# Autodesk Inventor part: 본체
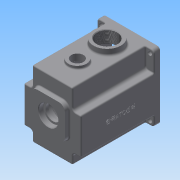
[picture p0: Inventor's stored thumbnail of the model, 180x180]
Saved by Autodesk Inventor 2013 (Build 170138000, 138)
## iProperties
Created: 2016-02
Part Number: 본체
Material: 알루미늄 6061
Document SubType Name: Modeling
Designer: mduedu
Density: 2.71 g/cm^3
Mass: 1353.73 g
Surface Area: 1142.22 cm^2
Volume: 499.533 cm^3
Author: mduedu
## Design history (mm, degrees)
sketch "스케치1"
  geometry: L1 (-47, -47)-(47, -47); L2 (47, -47)-(47, 63); L3 (47, 63)-(-47, 63); L4 (-47, 63)-(-47, -47); 2 further points
  constraints: 8 end point, 2 parallel, 1 horizontal, 1 midpoint, 1 perpendicular, 1 vertical alignment
  dimensions: "d0" = 94 distance of L2.end L3.end; "d155" = 110 distance of L1.end L2.end; "d156" = 47 distance from line of L1 point (0, 0)
extrude "돌출1" new body sketch "스케치1" distance "d2" = 130; taper "d3" = 0 deg
sketch "스케치3"
  geometry: C1 r 40 at (0, 0); 1 further point
  constraints: 1 centre point, 1 coincident
  dimensions: "d9" = 80 diameter of C1
extrude "돌출3" cut sketch "스케치3" distance "d11" = 121; taper "d12" = 0 deg
sketch "스케치4"
  geometry: C1 r 21 at (0, 11); 1 further point
  constraints: 1 centre point, 1 vertical alignment
  dimensions: "d13" = 21 radius of C1; "d15" = 11 distance of point (0, 0) C1.centre
extrude "돌출4" join sketch "스케치4" distance "d16" = 7; taper "d17" = 0 deg
sketch "스케치5"
  geometry: C1 r 15 at (0, -20); 1 further point
  constraints: 1 centre point, 1 vertical alignment
  dimensions: "d18" = 15 radius of C1; "d20" = 20 distance of point (0, 0) C1.centre
extrude "돌출5" join sketch "스케치5" distance "d21" = 7; taper "d22" = 0 deg
sketch "스케치6"
  geometry: L1 (-28, -17)-(28, -17); L2 (28, -17)-(28, 39); L3 (28, 39)-(-28, 39); L4 (-28, 39)-(-28, -17); L5 (-28, -17)-(28, 39); L6 (28, -17)-(-28, 39); C1 r 28 at (0, 11); A1 r 21 centre (0, 11) between (8.978, -7.984) and (-8.978, -7.984) reference; 1 further point
  constraints: 12 end point, 2 midpoint, 2 parallel, 2 tangent, 1 centre point, 1 coincident, 1 horizontal, 1 perpendicular
  dimensions: "d23" = 56 diameter of C1
extrude "돌출6" join sketch "스케치6" distance "d25" = 7; taper "d26" = -3 deg
hole "구멍1" diameter "d29" = 35; stored, may be unused: countersink angle "d33" = 90 deg, drill point angle "d35" = 0 deg; dims "d27" = 10, "d28" = 10, "d30" = 6, "d31" = 4, "d32" = 2, "d34" = 10
hole "구멍2" diameter "d38" = 22; stored, may be unused: countersink angle "d42" = 90 deg, drill point angle "d44" = 0 deg; dims "d36" = 10, "d37" = 10, "d39" = 6, "d40" = 4, "d41" = 2, "d43" = 7
hole "구멍3" diameter "d47" = 19; stored, may be unused: countersink angle "d51" = 90 deg, drill point angle "d53" = 0 deg; dims "d45" = 10, "d46" = 10, "d48" = 6, "d49" = 4, "d50" = 2, "d52" = 1
hole "구멍4" diameter "d56" = 32; stored, may be unused: countersink angle "d60" = 90 deg, drill point angle "d62" = 0 deg; dims "d57" = 6, "d58" = 4, "d59" = 2, "d61" = 8, "d220" = 10, "d221" = 10
hole "구멍5" diameter "d65" = 25; stored, may be unused: countersink angle "d69" = 90 deg, drill point angle "d71" = 0 deg; dims "d63" = 10, "d64" = 10, "d66" = 6, "d67" = 4, "d68" = 2, "d70" = 8
fillet "모깎기2" dims "d73" = 0.3
fillet "모깎기3" dims "d74" = 2
chamfer "모따기1" distance "d75" = 1; stored, may be unused: second distance "d76" = 2, angle "d77" = 45 deg
fillet "모깎기4" dims "d78" = 3
sketch "스케치16"
  geometry: L1 (-23, 32.726)-(23, 32.726); L2 (23, 32.726)-(23, 53); L3 (23, 53)-(-23, 53); L4 (-23, 53)-(-23, 32.726); L5 (-47, 63)-(47, 63) reference; 3 further points
  constraints: 8 end point, 2 parallel, 1 horizontal, 1 midpoint, 1 perpendicular, 1 vertical alignment, 2 other
  dimensions: "d160" = 46 distance of L2.end L3.end; "d163" = 10 distance between parallel lines of L3 L5
extrude "돌출15" cut sketch "스케치16" stored distance "d164" = 10; taper "d165" = 0 deg
fillet "모깎기5" dims "d79" = 2
fillet "모깎기15" dims "d166" = 5
sketch "스케치7"
  geometry: L1 (-23, 48)-(-23, 35.228) reference; L2 (23, 35.228)-(23, 48) reference; L3 (18, 53)-(-18, 53) reference; L4 (47, 63)-(47, -47) reference; L5 (47, -47)-(-47, -47) reference; L6 (-47, -47)-(-47, 63) reference; L7 (-47, 63)-(47, 63) reference; L8 (-26, 48)-(-26, 35.228); L9 (26, 35.228)-(26, 48); L10 (18, 56)-(-18, 56); C1 r 43 at (0, 0); A1 r 5 centre (-18, 48) between (-18, 53) and (-23, 48) reference; A2 r 5 centre (-28, 35.228) between (-24.889, 31.314) and (-23, 35.228) reference; A3 r 40 centre (0, 0) between (-24.889, 31.314) and (24.889, 31.314) reference; A4 r 5 centre (28, 35.228) between (23, 35.228) and (24.889, 31.314) reference; A5 r 5 centre (18, 48) between (23, 48) and (18, 53) reference; A6 r 8 centre (-18, 48) between (-18, 56) and (-26, 48); A7 r 2 centre (-28, 35.228) between (-26.756, 33.662) and (-26, 35.228); A8 r 43 centre (0, 0) between (-26.756, 33.662) and (26.756, 33.662); A9 r 2 centre (28, 35.228) between (26, 35.228) and (26.756, 33.662); A10 r 8 centre (18, 48) between (26, 48) and (18, 56); 1 further point
  constraints: 10 point on circle, 6 centre point, 6 end point, 1 coincident, 7 other
  dimensions: "d80" = 86 diameter of C1; "d167" = 3 distance between parallel lines of L3 L10
extrude "돌출7" cut sketch "스케치7" distance "d83" = 9; taper "d84" = 0 deg
sketch "스케치8" dims "d168" = 36
  geometry: L1 (-36, 4)-(-39.799, 4); L2 (-36, -4)-(-39.799, -4); A1 r 4 centre (-36, 0) between (-36, 4) and (-36, -4); A2 r 40 centre (0, 0) between (-24.889, 31.314) and (24.889, 31.314) reference; A3 r 40 centre (0, 0) between (-39.799, 4) and (-39.799, -4); 2 further points
  constraints: 5 point on circle, 4 end point, 2 centre point, 2 coincident, 2 horizontal alignment, 2 tangent, 1 horizontal, 1 parallel, 2 other
  dimensions: "d169" = 4 radius of A1
extrude "돌출9" join sketch "스케치8" stored distance "d89" = 9; taper "d90" = 0 deg
fillet "모깎기6" dims "d91" = 3.5
node "작업 평면1"
sketch "스케치9"
  geometry: L1 (47, 63)-(33, 63); L2 (33, 63)-(33, 30); L3 (33, 30)-(47, 30); L4 (47, 30)-(47, 63); L5 (47, 63)-(-47, 63) reference; L6 (47, -47)-(47, 63) reference; A1 r 40 centre (0, 0) between (-39.148, -8.214) and (39.148, -8.214) reference; 1 further point
  constraints: 8 end point, 2 parallel, 1 coincident, 1 horizontal, 1 perpendicular
  dimensions: "d95" = 33 distance from line of L2 point (0, 0); "d96" = 30 distance from line of L3 point (0, 0)
extrude "돌출10" cut sketch "스케치9" distance "d97" = 110; taper "d98" = 0 deg
extrude "돌출21" cut sketch "스케치9" stored distance "d217" = 10; taper "d218" = 0 deg
sketch "스케치11" dims "d20" = 20
  geometry: L1 (-40, -40)-(40, -40); L2 (40, -40)-(40, 56); L3 (40, 56)-(-40, 56); L4 (-40, 56)-(-40, -40); L5 (-47, -47)-(47, -47) reference; L6 (47, 63)-(-47, 63) reference; L7 (-47, 63)-(-47, -47) reference; C1 r 3.5 at (-40, 56); C2 r 3.5 at (40, 56); C3 r 3.5 at (40, -40); C4 r 3.5 at (-40, -40); 1 further point
  constraints: 8 end point, 4 centre point, 4 coincident, 3 equal radius, 2 parallel, 1 horizontal, 1 perpendicular
  dimensions: "d109" = 80 distance of L2.end L3.end; "d112" = 7 diameter of C1; "d157" = 7 distance from line of L1.start L5; "d158" = 7 distance between parallel lines of L6 L3; "d159" = 7 distance from line of L7 L3.end
extrude "돌출12" cut sketch "스케치11" stored distance "d113" = 63; taper "d114" = 0 deg
fillet "모깎기7" dims "d115" = 5, "d187" = 5
fillet "모깎기8" dims "d116" = 5
fillet "모깎기18" dims "d219" = 2
fillet "모깎기12" dims "d120" = 2
fillet "모깎기13" dims "d121" = 2
sketch "스케치12"
  geometry: 3 further points
  constraints: 2 horizontal alignment
hole "구멍6" sketch "스케치12" at (36, 0), (-36, 0) diameter "d122" = 3.242; stored, may be unused: countersink angle "d126" = 90 deg, drill point angle "d128" = 120 deg; dims "d123" = 7, "d124" = 4, "d125" = 2, "d127" = 9
fillet "모깎기14" dims "d147" = 10
chamfer "모따기4" distance "d151" = 1; stored, may be unused: second distance "d152" = 2, angle "d153" = 45 deg
sketch "스케치20"
  geometry: L1 (73, -12)-(73, -130) reference; L2 (84, -8)-(77, -8) reference; L3 (84, 0)-(84, -8) reference; L4 (84, 0)-(0, 0) reference; L5 (7, -8)-(0, -8) reference; L6 (11, -130)-(11, -12) reference; L7 (0, -8)-(0, 0) reference; L8 (73, -130)-(11, -130) reference; L9 (42, 0)-(42, -130); C1 r 10 at (42, -89); A1 r 4 centre (77, -12) between (77, -8) and (73, -12) reference; A2 r 4 centre (7, -12) between (11, -12) and (7, -8) reference
  constraints: 2 end point, 1 centre point, 1 midpoint, 1 point on line
  dimensions: "d189" = 20 diameter of C1; "d190" = 41 distance from line of C1.centre L8
extrude "돌출19" cut sketch "스케치20" stored distance "d191" = 10; taper "d192" = 0 deg
sketch "스케치18"
  geometry: C1 r 15 at (42, -89); C2 r 10 at (42, -89) reference; 1 further point
  constraints: 1 centre point, 1 concentric
  dimensions: "d174" = 30 diameter of C1
extrude "돌출17" join sketch "스케치18" distance "d175" = 5; taper "d176" = 0 deg
fillet "모깎기16" dims "d177" = 2
sketch "스케치19"
  geometry: C1 r 10 at (18, 80) reference; C2 r 15 at (18, 80); 1 further point
  constraints: 1 centre point, 1 coincident
  dimensions: "d178" = 30 diameter of C2
extrude "돌출18" cut sketch "스케치19" distance "d181" = 5; taper "d182" = 0 deg
chamfer "모따기5" distance "d183" = 0.5; stored, may be unused: second distance "d184" = 2, angle "d185" = 45 deg
sketch "스케치21"
  geometry: L1 (-12, 14)-(-130, 14) reference; L2 (-8, 0)-(-8, 10) reference; L3 (0, 0)-(0, 100) reference; L4 (-8, 100)-(0, 100) reference; L5 (-8, 74)-(-8, 100) reference; L6 (-130, 70)-(-12, 70) reference; L7 (-130, 14)-(-130, 70) reference; L8 (0, 0)-(-8, 0) reference; L9 (-130, 14)-(-130, 70) reference; L10 (27.4, 42)-(-164.4, 42) reference; A1 r 4 centre (-12, 74) between (-12, 70) and (-8, 74) reference; A2 r 4 centre (-12, 10) between (-8, 10) and (-12, 14) reference; 3 further points
  constraints: 1 coincident, 1 point on line, 1 other
  dimensions: "d222" = 65 distance from line of point (-65, 42) L9
feature "엠보싱2" sketch "스케치21" dims "d20" = 20, "d193" = 0.5, "d194" = 0
sketch "스케치22"
  geometry: L1 (73, -12)-(73, -130) reference; L2 (84, -8)-(77, -8) reference; L3 (84, 0)-(84, -8) reference; L4 (84, 0)-(0, 0) reference; L5 (7, -8)-(0, -8) reference; L6 (11, -130)-(11, -12) reference; L7 (0, -8)-(0, 0) reference; L8 (73, -130)-(11, -130) reference; L9 (42, -130)-(42, 0); C1 r 17 at (42, -89) reference; C2 r 22.5 at (42, -40); A1 r 4 centre (77, -12) between (77, -8) and (73, -12) reference; A2 r 4 centre (7, -12) between (11, -12) and (7, -8) reference
  constraints: 2 end point, 1 centre point, 1 midpoint, 1 point on line
  dimensions: "d195" = 45 diameter of C2; "d197" = 40 distance from line of C2.centre L4
extrude "돌출20" join sketch "스케치22" distance "d198" = 10; taper "d199" = 0 deg
fillet "모깎기17" dims "d200" = 3
hole "구멍7" diameter "d203" = 33.376; stored, may be unused: countersink angle "d207" = 90 deg, drill point angle "d209" = 118 deg; dims "d204" = 6, "d205" = 4, "d206" = 2, "d208" = 8, "d223" = 10, "d224" = 10
chamfer "모따기6" distance "d210" = 1; stored, may be unused: second distance "d211" = 2, angle "d212" = 45 deg
fillet "모깎기19" dims "d225" = 2
node "솔리드1"
pattern_circular "원형 패턴1" dims angle "d93" = 360 deg
mirror "대칭1"
mirror "대칭2"
node "투영된 루프1"
node "투영된 루프2"
node "투영된 루프3"
node "절단 모서리 투영3"
